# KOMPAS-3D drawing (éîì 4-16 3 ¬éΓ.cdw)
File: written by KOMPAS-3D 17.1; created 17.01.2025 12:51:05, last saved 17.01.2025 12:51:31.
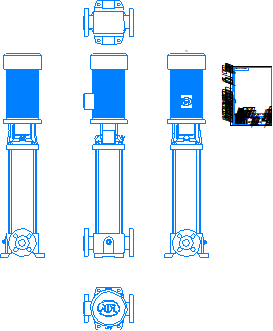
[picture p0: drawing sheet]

Sheet 1: A4, portrait

Title block, sheet 1: name: ВМН 4-16 3 кВт; designation: ВМН 4-16 3 кВт; material: Сталь 10  ГОСТ 1050-2013; mass: 141,86; sheets: 1; sheet format: A4; stored path: \\adlc.lan\data\АДЛ_ПКД\3D-модели\ADL production\Насосы ГРАНПАМП\Насосы ВМН\ВМН4\KOMPAS 3D\ВМН 4-16 3 кВт.cdw

Views: Вид 1, Спереди, Проекционный вид 2, Проекционный вид 3, Проекционный вид 4, Проекционный вид 5
Referenced files in \\adlc.lan\data\АДЛ_ПКД\3D-модели\ADL production\Насосы ГРАНПАМП\Насосы ВМН\ВМН4\KOMPAS 3D\: ВМН 4-16 3 кВт.m3d
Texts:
  Andrey
  АДЛ
Dimensions and other numbers on the sheet: 1:1; 1; 141,86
